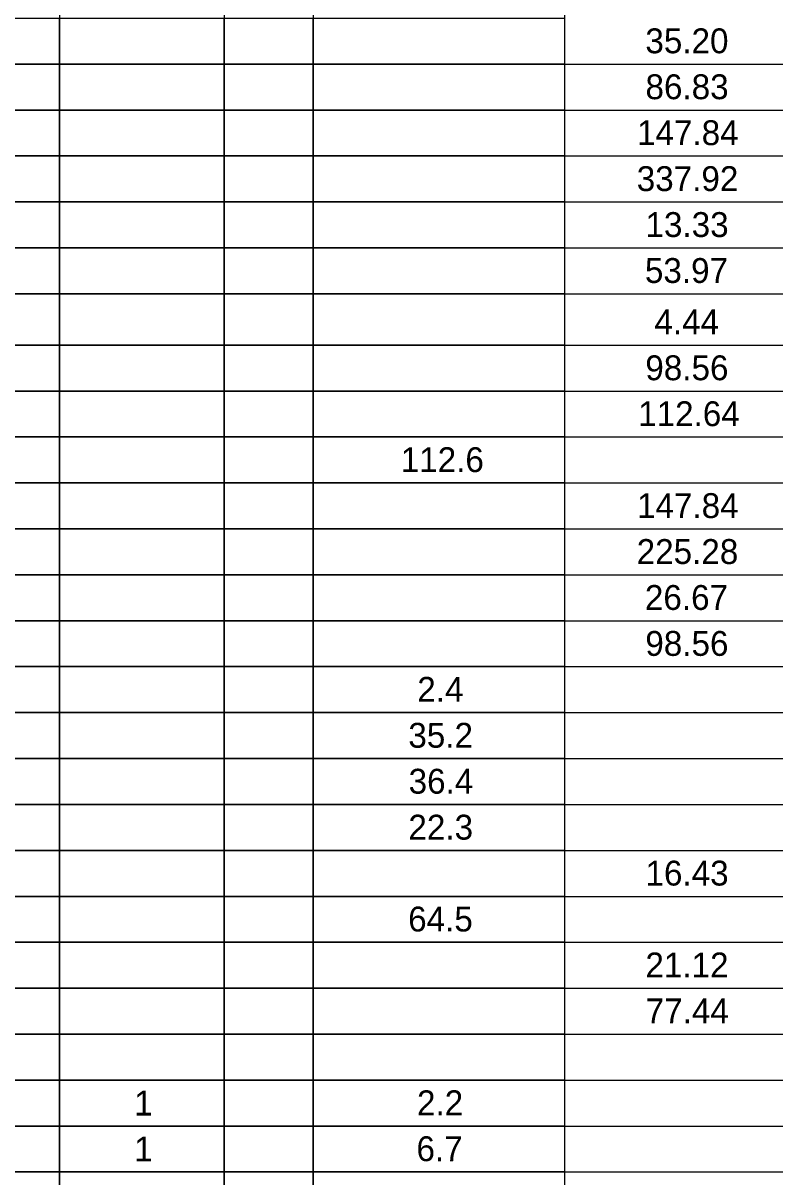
# Model space of a CAD drawing. Extents: x 0 to 34, y 0 to 22.
# Drawn here: x 12.61 to 16.79, y 4.54 to 10.94 of the extents above; entities that cross this region are included whole.
import ezdxf

# ---------------------------------------------------------------- set-up
doc = ezdxf.new("R2010")
doc.units = 0
doc.layers.add('Default', color=7, linetype='Continuous')

msp = doc.modelspace()

# ---------------------------------------------------------------- linework, layer by layer
at = {"layer": 'Default'}
for p, q in [((14.2264, 21.4685), (14.2264, 0.8435)), ((15.6214, 21.4685), (15.6214, 0.8435)), ((12.8164, 18.9335), (12.8164, 1.2485)), ((13.7314, 18.9335), (13.7314, 1.2485)), ((4.7014, 10.7135), (28.7614, 10.7135)), ((4.7014, 10.4585), (28.7614, 10.4585)), ((4.7014, 10.2035), (28.7614, 10.2035)), ((4.7014, 9.9485), (28.7614, 9.9485)), ((4.7014, 9.6935), (28.7614, 9.6935)), ((4.7014, 9.4385), (28.7614, 9.4385)), ((4.7014, 9.1535), (28.7614, 9.1535)), ((4.7014, 8.8985), (28.7614, 8.8985)), ((4.7014, 8.6435), (28.7614, 8.6435)), ((4.7014, 8.3885), (28.7614, 8.3885)), ((4.7014, 8.1335), (28.7614, 8.1335)), ((4.7014, 7.8785), (28.7614, 7.8785)), ((4.7014, 7.6235), (28.7614, 7.6235)), ((4.7014, 7.3685), (28.7614, 7.3685)), ((4.7014, 7.1135), (28.7614, 7.1135)), ((4.7014, 6.8585), (28.7614, 6.8585)), ((4.7014, 6.6035), (28.7614, 6.6035)), ((4.7014, 6.3485), (28.7614, 6.3485)), ((4.7014, 6.0935), (28.7614, 6.0935)), ((4.7014, 5.8385), (28.7614, 5.8385)), ((4.7014, 5.5835), (28.7614, 5.5835)), ((4.7014, 5.3285), (28.7614, 5.3285)), ((4.7014, 5.0735), (28.7614, 5.0735)), ((4.7014, 4.8185), (28.7614, 4.8185)), ((4.7014, 4.5635), (28.7614, 4.5635))]:
    msp.add_line(p, q, dxfattribs=at)
for points in [[(12.3214, 10.9685), (12.8164, 10.9685), (12.8164, 10.7135), (12.3214, 10.7135)], [(12.8164, 10.9685), (13.7314, 10.9685), (13.7314, 10.7135), (12.8164, 10.7135)], [(13.7314, 10.9685), (14.2264, 10.9685), (14.2264, 10.7135), (13.7314, 10.7135)], [(14.2264, 10.9685), (15.6214, 10.9685), (15.6214, 10.7135), (14.2264, 10.7135)], [(12.3214, 10.7135), (12.8164, 10.7135), (12.8164, 10.4585), (12.3214, 10.4585)], [(12.8164, 10.7135), (13.7314, 10.7135), (13.7314, 10.4585), (12.8164, 10.4585)], [(13.7314, 10.7135), (14.2264, 10.7135), (14.2264, 10.4585), (13.7314, 10.4585)], [(14.2264, 10.7135), (15.6214, 10.7135), (15.6214, 10.4585), (14.2264, 10.4585)], [(12.3214, 10.4585), (12.8164, 10.4585), (12.8164, 10.2035), (12.3214, 10.2035)], [(12.8164, 10.4585), (13.7314, 10.4585), (13.7314, 10.2035), (12.8164, 10.2035)], [(13.7314, 10.4585), (14.2264, 10.4585), (14.2264, 10.2035), (13.7314, 10.2035)], [(14.2264, 10.4585), (15.6214, 10.4585), (15.6214, 10.2035), (14.2264, 10.2035)], [(12.3214, 10.2035), (12.8164, 10.2035), (12.8164, 9.9485), (12.3214, 9.9485)], [(12.8164, 10.2035), (13.7314, 10.2035), (13.7314, 9.9485), (12.8164, 9.9485)], [(13.7314, 10.2035), (14.2264, 10.2035), (14.2264, 9.9485), (13.7314, 9.9485)], [(14.2264, 10.2035), (15.6214, 10.2035), (15.6214, 9.9485), (14.2264, 9.9485)], [(12.3214, 9.9485), (12.8164, 9.9485), (12.8164, 9.6935), (12.3214, 9.6935)], [(12.8164, 9.9485), (13.7314, 9.9485), (13.7314, 9.6935), (12.8164, 9.6935)], [(13.7314, 9.9485), (14.2264, 9.9485), (14.2264, 9.6935), (13.7314, 9.6935)], [(14.2264, 9.9485), (15.6214, 9.9485), (15.6214, 9.6935), (14.2264, 9.6935)], [(12.3214, 9.6935), (12.8164, 9.6935), (12.8164, 9.4385), (12.3214, 9.4385)], [(12.8164, 9.6935), (13.7314, 9.6935), (13.7314, 9.4385), (12.8164, 9.4385)], [(13.7314, 9.6935), (14.2264, 9.6935), (14.2264, 9.4385), (13.7314, 9.4385)], [(14.2264, 9.6935), (15.6214, 9.6935), (15.6214, 9.4385), (14.2264, 9.4385)], [(12.3214, 9.4385), (12.8164, 9.4385), (12.8164, 9.1535), (12.3214, 9.1535)], [(12.8164, 9.4385), (13.7314, 9.4385), (13.7314, 9.1535), (12.8164, 9.1535)], [(13.7314, 9.4385), (14.2264, 9.4385), (14.2264, 9.1535), (13.7314, 9.1535)], [(14.2264, 9.4385), (15.6214, 9.4385), (15.6214, 9.1535), (14.2264, 9.1535)], [(12.3214, 9.1535), (12.8164, 9.1535), (12.8164, 8.8985), (12.3214, 8.8985)], [(12.8164, 9.1535), (13.7314, 9.1535), (13.7314, 8.8985), (12.8164, 8.8985)], [(13.7314, 9.1535), (14.2264, 9.1535), (14.2264, 8.8985), (13.7314, 8.8985)], [(14.2264, 9.1535), (15.6214, 9.1535), (15.6214, 8.8985), (14.2264, 8.8985)], [(12.3214, 8.8985), (12.8164, 8.8985), (12.8164, 8.6435), (12.3214, 8.6435)], [(12.8164, 8.8985), (13.7314, 8.8985), (13.7314, 8.6435), (12.8164, 8.6435)], [(13.7314, 8.8985), (14.2264, 8.8985), (14.2264, 8.6435), (13.7314, 8.6435)], [(14.2264, 8.8985), (15.6214, 8.8985), (15.6214, 8.6435), (14.2264, 8.6435)], [(12.3214, 8.6435), (12.8164, 8.6435), (12.8164, 8.3885), (12.3214, 8.3885)], [(12.8164, 8.6435), (13.7314, 8.6435), (13.7314, 8.3885), (12.8164, 8.3885)], [(13.7314, 8.6435), (14.2264, 8.6435), (14.2264, 8.3885), (13.7314, 8.3885)], [(14.2264, 8.6435), (15.6214, 8.6435), (15.6214, 8.3885), (14.2264, 8.3885)], [(12.3214, 8.3885), (12.8164, 8.3885), (12.8164, 8.1335), (12.3214, 8.1335)], [(12.8164, 8.3885), (13.7314, 8.3885), (13.7314, 8.1335), (12.8164, 8.1335)], [(13.7314, 8.3885), (14.2264, 8.3885), (14.2264, 8.1335), (13.7314, 8.1335)], [(14.2264, 8.3885), (15.6214, 8.3885), (15.6214, 8.1335), (14.2264, 8.1335)], [(12.3214, 8.1335), (12.8164, 8.1335), (12.8164, 7.8785), (12.3214, 7.8785)], [(12.8164, 8.1335), (13.7314, 8.1335), (13.7314, 7.8785), (12.8164, 7.8785)], [(13.7314, 8.1335), (14.2264, 8.1335), (14.2264, 7.8785), (13.7314, 7.8785)], [(14.2264, 8.1335), (15.6214, 8.1335), (15.6214, 7.8785), (14.2264, 7.8785)], [(12.3214, 7.8785), (12.8164, 7.8785), (12.8164, 7.6235), (12.3214, 7.6235)], [(12.8164, 7.8785), (13.7314, 7.8785), (13.7314, 7.6235), (12.8164, 7.6235)], [(13.7314, 7.8785), (14.2264, 7.8785), (14.2264, 7.6235), (13.7314, 7.6235)], [(14.2264, 7.8785), (15.6214, 7.8785), (15.6214, 7.6235), (14.2264, 7.6235)], [(12.3214, 7.6235), (12.8164, 7.6235), (12.8164, 7.3685), (12.3214, 7.3685)], [(12.8164, 7.6235), (13.7314, 7.6235), (13.7314, 7.3685), (12.8164, 7.3685)], [(13.7314, 7.6235), (14.2264, 7.6235), (14.2264, 7.3685), (13.7314, 7.3685)], [(14.2264, 7.6235), (15.6214, 7.6235), (15.6214, 7.3685), (14.2264, 7.3685)], [(12.3214, 7.3685), (12.8164, 7.3685), (12.8164, 7.1135), (12.3214, 7.1135)], [(12.8164, 7.3685), (13.7314, 7.3685), (13.7314, 7.1135), (12.8164, 7.1135)], [(13.7314, 7.3685), (14.2264, 7.3685), (14.2264, 7.1135), (13.7314, 7.1135)], [(14.2264, 7.3685), (15.6214, 7.3685), (15.6214, 7.1135), (14.2264, 7.1135)], [(12.3214, 7.1135), (12.8164, 7.1135), (12.8164, 6.8585), (12.3214, 6.8585)], [(12.8164, 7.1135), (13.7314, 7.1135), (13.7314, 6.8585), (12.8164, 6.8585)], [(13.7314, 7.1135), (14.2264, 7.1135), (14.2264, 6.8585), (13.7314, 6.8585)], [(14.2264, 7.1135), (15.6214, 7.1135), (15.6214, 6.8585), (14.2264, 6.8585)], [(12.3214, 6.8585), (12.8164, 6.8585), (12.8164, 6.6035), (12.3214, 6.6035)], [(12.8164, 6.8585), (13.7314, 6.8585), (13.7314, 6.6035), (12.8164, 6.6035)], [(13.7314, 6.8585), (14.2264, 6.8585), (14.2264, 6.6035), (13.7314, 6.6035)], [(14.2264, 6.8585), (15.6214, 6.8585), (15.6214, 6.6035), (14.2264, 6.6035)], [(12.3214, 6.6035), (12.8164, 6.6035), (12.8164, 6.3485), (12.3214, 6.3485)], [(12.8164, 6.6035), (13.7314, 6.6035), (13.7314, 6.3485), (12.8164, 6.3485)], [(13.7314, 6.6035), (14.2264, 6.6035), (14.2264, 6.3485), (13.7314, 6.3485)], [(14.2264, 6.6035), (15.6214, 6.6035), (15.6214, 6.3485), (14.2264, 6.3485)], [(12.3214, 6.3485), (12.8164, 6.3485), (12.8164, 6.0935), (12.3214, 6.0935)], [(12.8164, 6.3485), (13.7314, 6.3485), (13.7314, 6.0935), (12.8164, 6.0935)], [(13.7314, 6.3485), (14.2264, 6.3485), (14.2264, 6.0935), (13.7314, 6.0935)], [(14.2264, 6.3485), (15.6214, 6.3485), (15.6214, 6.0935), (14.2264, 6.0935)], [(12.3214, 6.0935), (12.8164, 6.0935), (12.8164, 5.8385), (12.3214, 5.8385)], [(12.8164, 6.0935), (13.7314, 6.0935), (13.7314, 5.8385), (12.8164, 5.8385)], [(13.7314, 6.0935), (14.2264, 6.0935), (14.2264, 5.8385), (13.7314, 5.8385)], [(14.2264, 6.0935), (15.6214, 6.0935), (15.6214, 5.8385), (14.2264, 5.8385)], [(12.3214, 5.8385), (12.8164, 5.8385), (12.8164, 5.5835), (12.3214, 5.5835)], [(12.8164, 5.8385), (13.7314, 5.8385), (13.7314, 5.5835), (12.8164, 5.5835)], [(13.7314, 5.8385), (14.2264, 5.8385), (14.2264, 5.5835), (13.7314, 5.5835)], [(14.2264, 5.8385), (15.6214, 5.8385), (15.6214, 5.5835), (14.2264, 5.5835)], [(12.3214, 5.5835), (12.8164, 5.5835), (12.8164, 5.3285), (12.3214, 5.3285)], [(12.8164, 5.5835), (13.7314, 5.5835), (13.7314, 5.3285), (12.8164, 5.3285)], [(13.7314, 5.5835), (14.2264, 5.5835), (14.2264, 5.3285), (13.7314, 5.3285)], [(14.2264, 5.5835), (15.6214, 5.5835), (15.6214, 5.3285), (14.2264, 5.3285)], [(12.3214, 5.3285), (12.8164, 5.3285), (12.8164, 5.0735), (12.3214, 5.0735)], [(12.8164, 5.3285), (13.7314, 5.3285), (13.7314, 5.0735), (12.8164, 5.0735)], [(13.7314, 5.3285), (14.2264, 5.3285), (14.2264, 5.0735), (13.7314, 5.0735)], [(14.2264, 5.3285), (15.6214, 5.3285), (15.6214, 5.0735), (14.2264, 5.0735)], [(12.3214, 5.0735), (12.8164, 5.0735), (12.8164, 4.8185), (12.3214, 4.8185)], [(12.8164, 5.0735), (13.7314, 5.0735), (13.7314, 4.8185), (12.8164, 4.8185)], [(13.7314, 5.0735), (14.2264, 5.0735), (14.2264, 4.8185), (13.7314, 4.8185)], [(14.2264, 5.0735), (15.6214, 5.0735), (15.6214, 4.8185), (14.2264, 4.8185)], [(12.3214, 4.8185), (12.8164, 4.8185), (12.8164, 4.5635), (12.3214, 4.5635)], [(12.8164, 4.8185), (13.7314, 4.8185), (13.7314, 4.5635), (12.8164, 4.5635)], [(13.7314, 4.8185), (14.2264, 4.8185), (14.2264, 4.5635), (13.7314, 4.5635)], [(14.2264, 4.8185), (15.6214, 4.8185), (15.6214, 4.5635), (14.2264, 4.5635)], [(12.3214, 4.5635), (12.8164, 4.5635), (12.8164, 4.3085), (12.3214, 4.3085)], [(12.8164, 4.5635), (13.7314, 4.5635), (13.7314, 4.3085), (12.8164, 4.3085)], [(13.7314, 4.5635), (14.2264, 4.5635), (14.2264, 4.3085), (13.7314, 4.3085)], [(14.2264, 4.5635), (15.6214, 4.5635), (15.6214, 4.3085), (14.2264, 4.3085)]]:
    msp.add_lwpolyline(points, close=True, dxfattribs=at)

# ---------------------------------------------------------------- texts
for s, p in [('35.20', (16.0711, 10.7735)), ('86.83', (16.0718, 10.5185)), ('147.84', (16.0247, 10.2635)), ('337.92', (16.0231, 10.0085)), ('13.33', (16.0718, 9.7535)), ('53.97', (16.0685, 9.4985)), ('4.44', (16.1212, 9.2135)), ('98.56', (16.0709, 8.9585)), ('112.64', (16.0311, 8.7035)), ('112.6', (14.7123, 8.4485)), ('147.84', (16.0247, 8.1935)), ('225.28', (16.0229, 7.9385)), ('26.67', (16.0685, 7.6835)), ('98.56', (16.0709, 7.4285)), ('2.4', (14.8044, 7.1735)), ('35.2', (14.7546, 6.9185)), ('36.4', (14.7562, 6.6635)), ('22.3', (14.755, 6.4085)), ('16.43', (16.0718, 6.1535)), ('64.5', (14.7537, 5.8985)), ('21.12', (16.0714, 5.6435)), ('77.44', (16.0729, 5.3885)), ('1', (13.2324, 4.877)), ('2.2', (14.8028, 4.8785)), ('1', (13.2324, 4.622)), ('6.7', (14.7999, 4.6235))]:
    msp.add_text(s, height=0.138, dxfattribs=at).set_placement(p)

doc.saveas('drawing.dxf')
